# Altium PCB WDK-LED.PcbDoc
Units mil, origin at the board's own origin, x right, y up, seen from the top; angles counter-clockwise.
Board outline 1260 x 1260 mil, 2 copper layers (Top Layer, Bottom Layer); 26 components, 16 nets, 111 pads, 25 vias.
Unrouted connection lines stored in the file: 19.
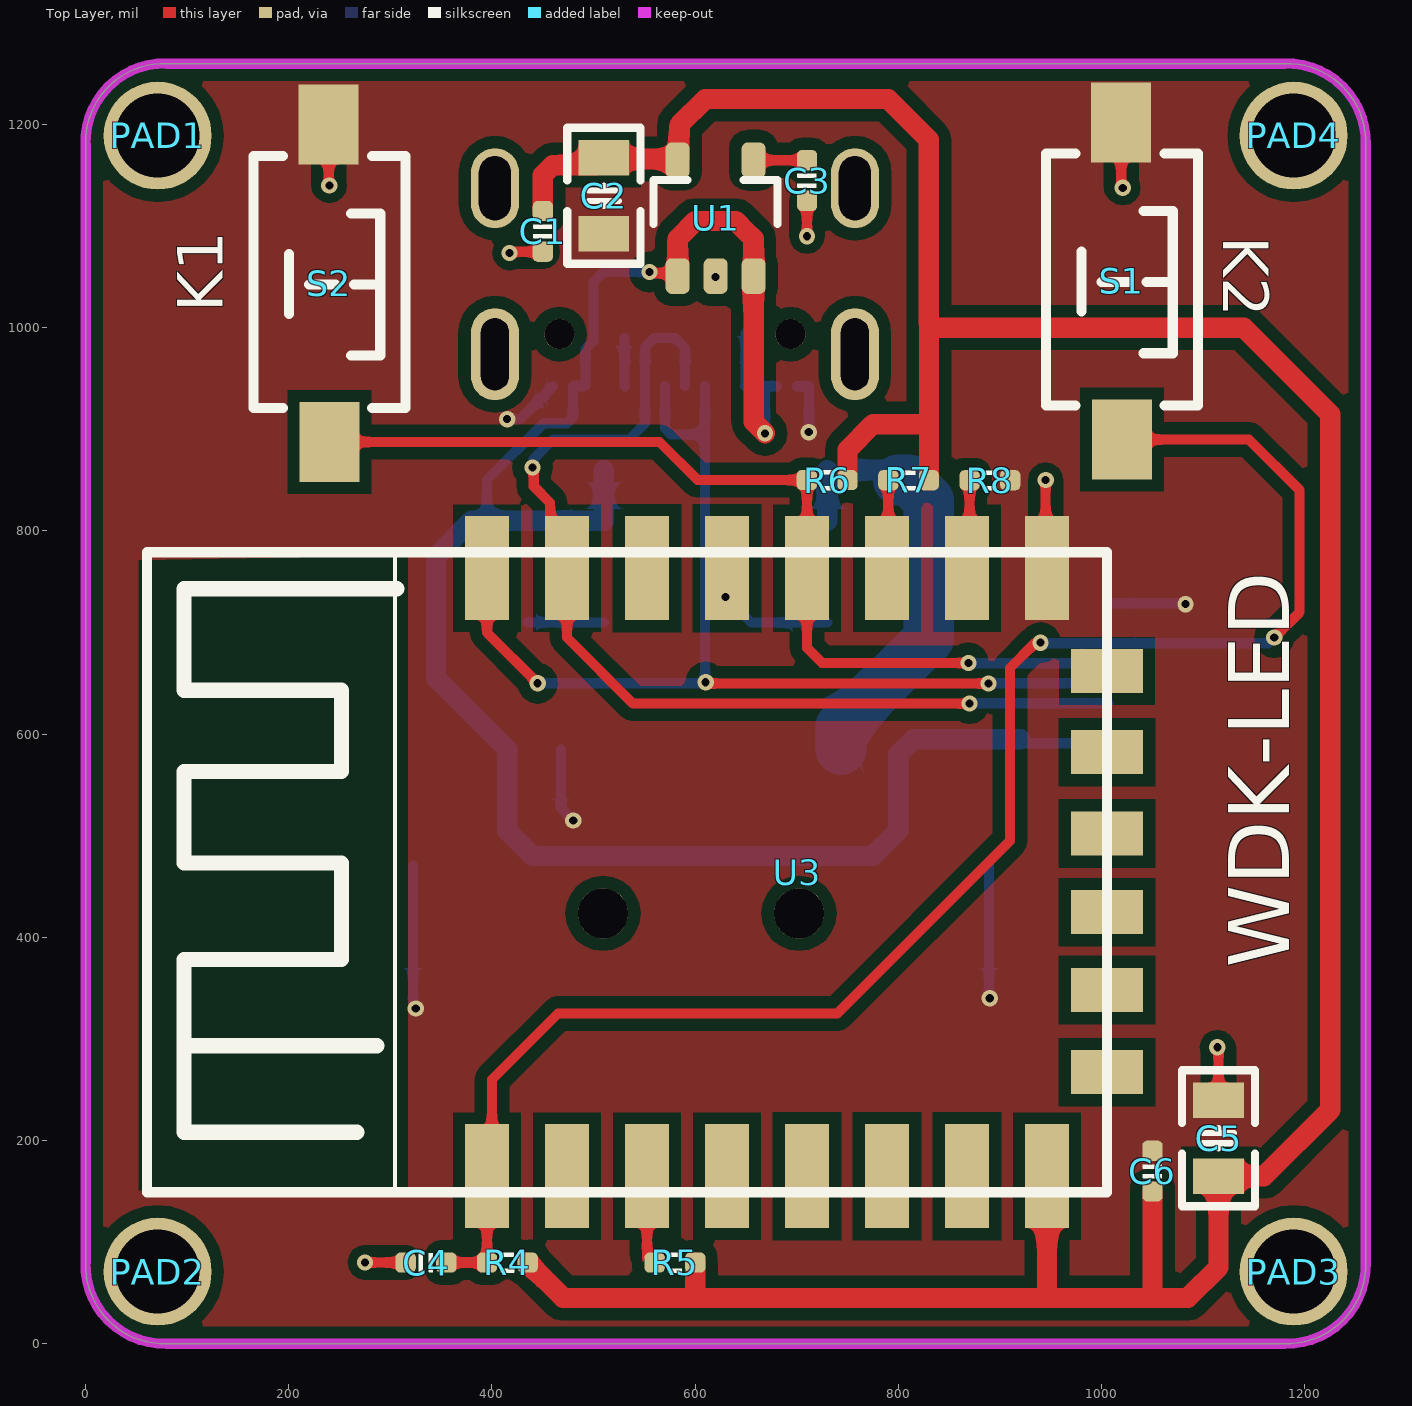
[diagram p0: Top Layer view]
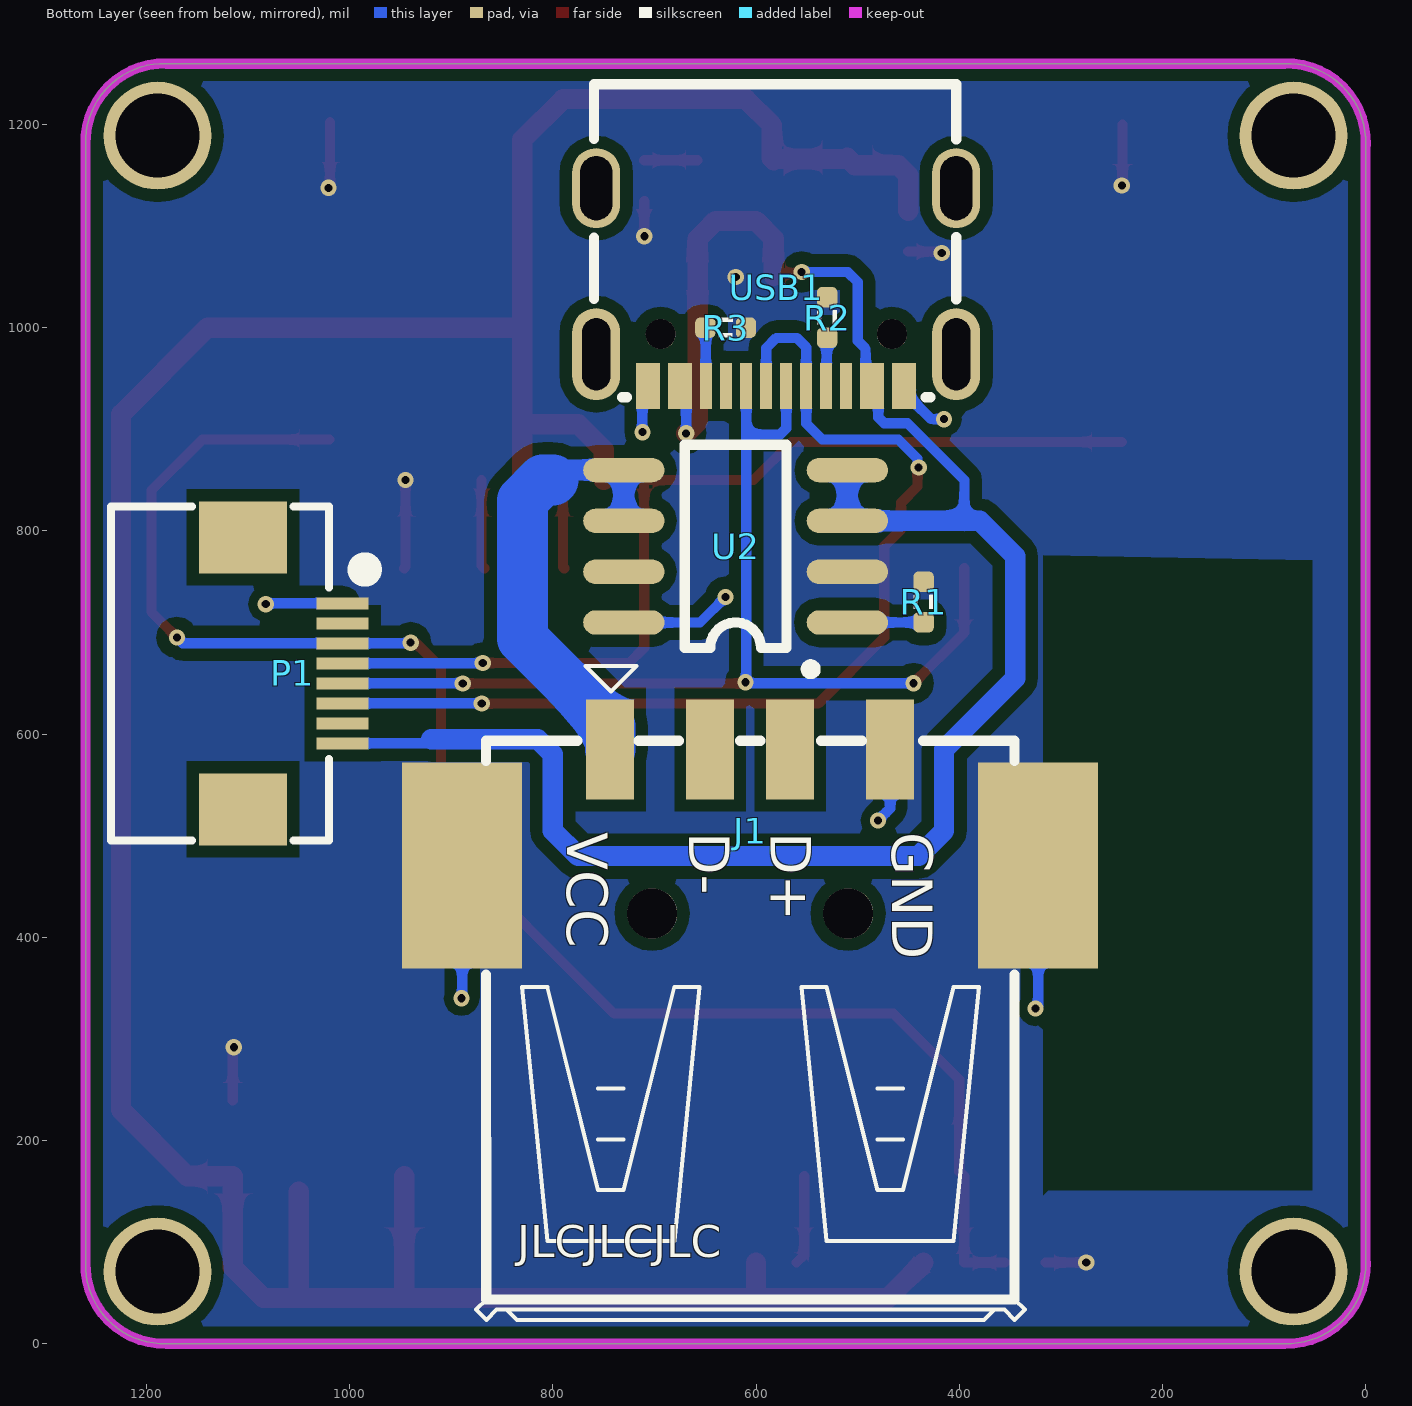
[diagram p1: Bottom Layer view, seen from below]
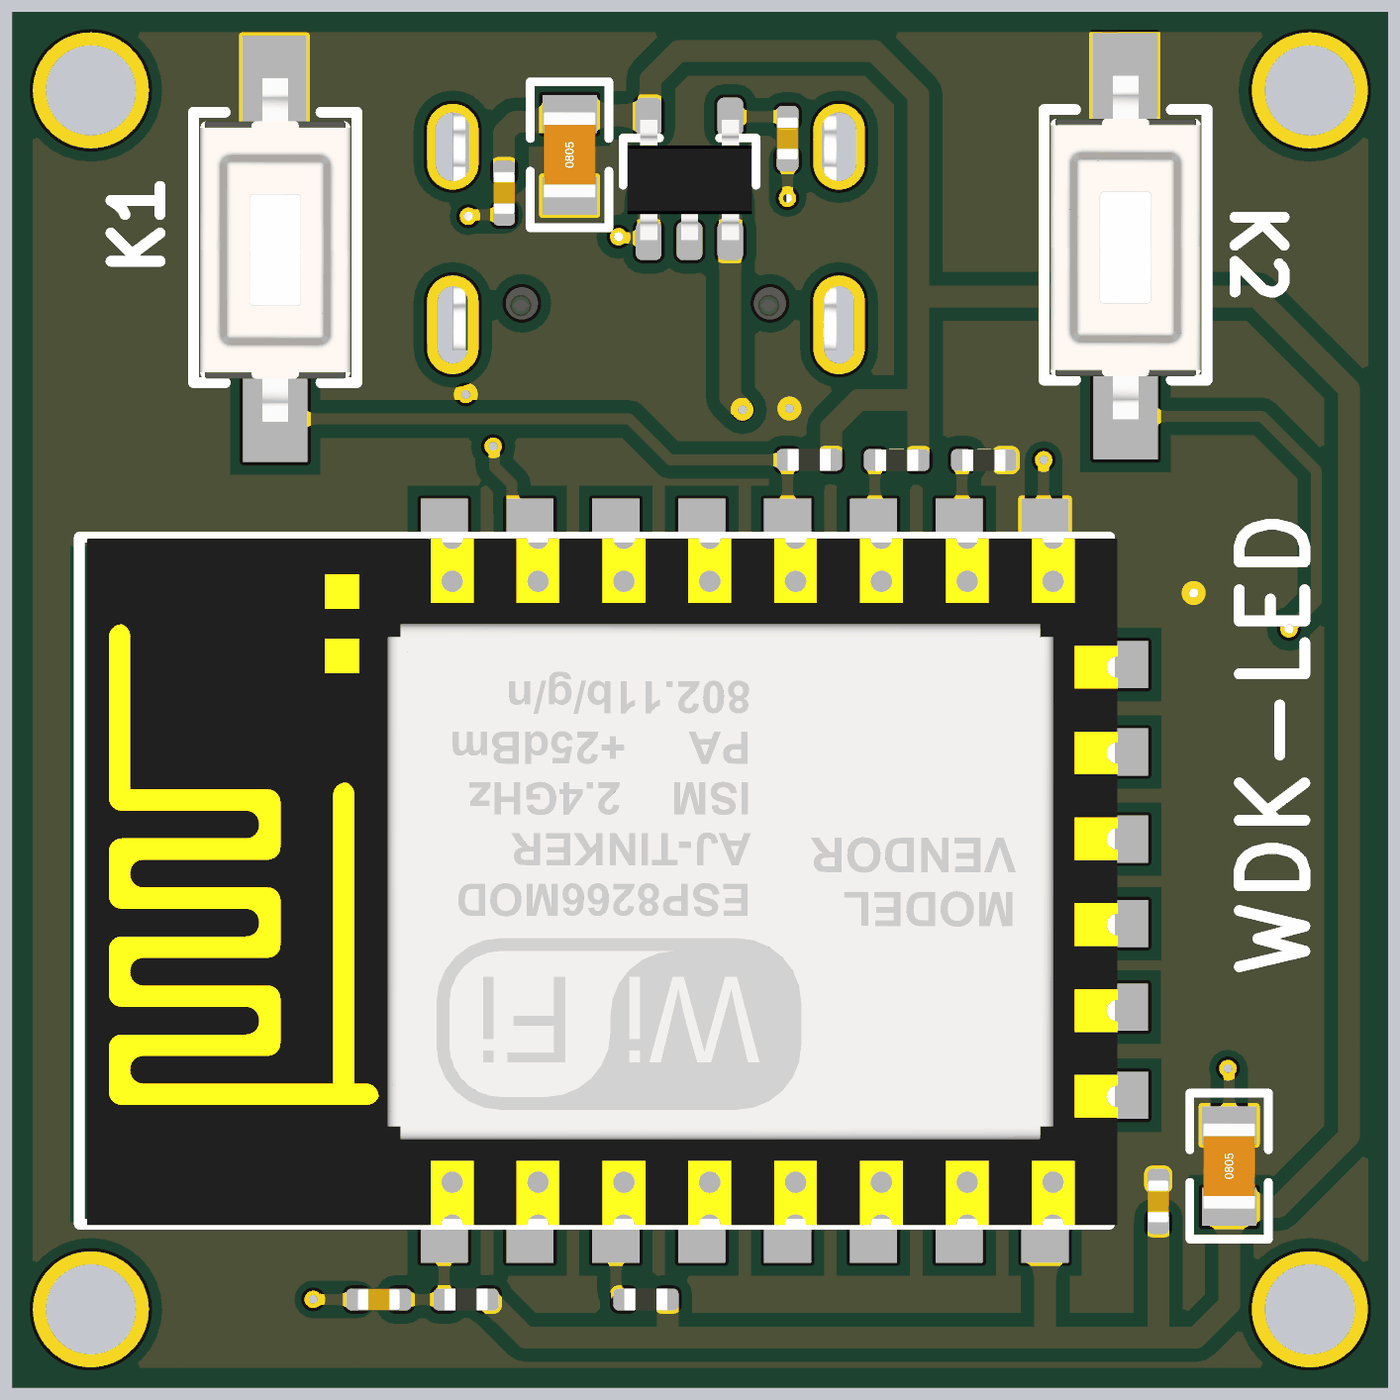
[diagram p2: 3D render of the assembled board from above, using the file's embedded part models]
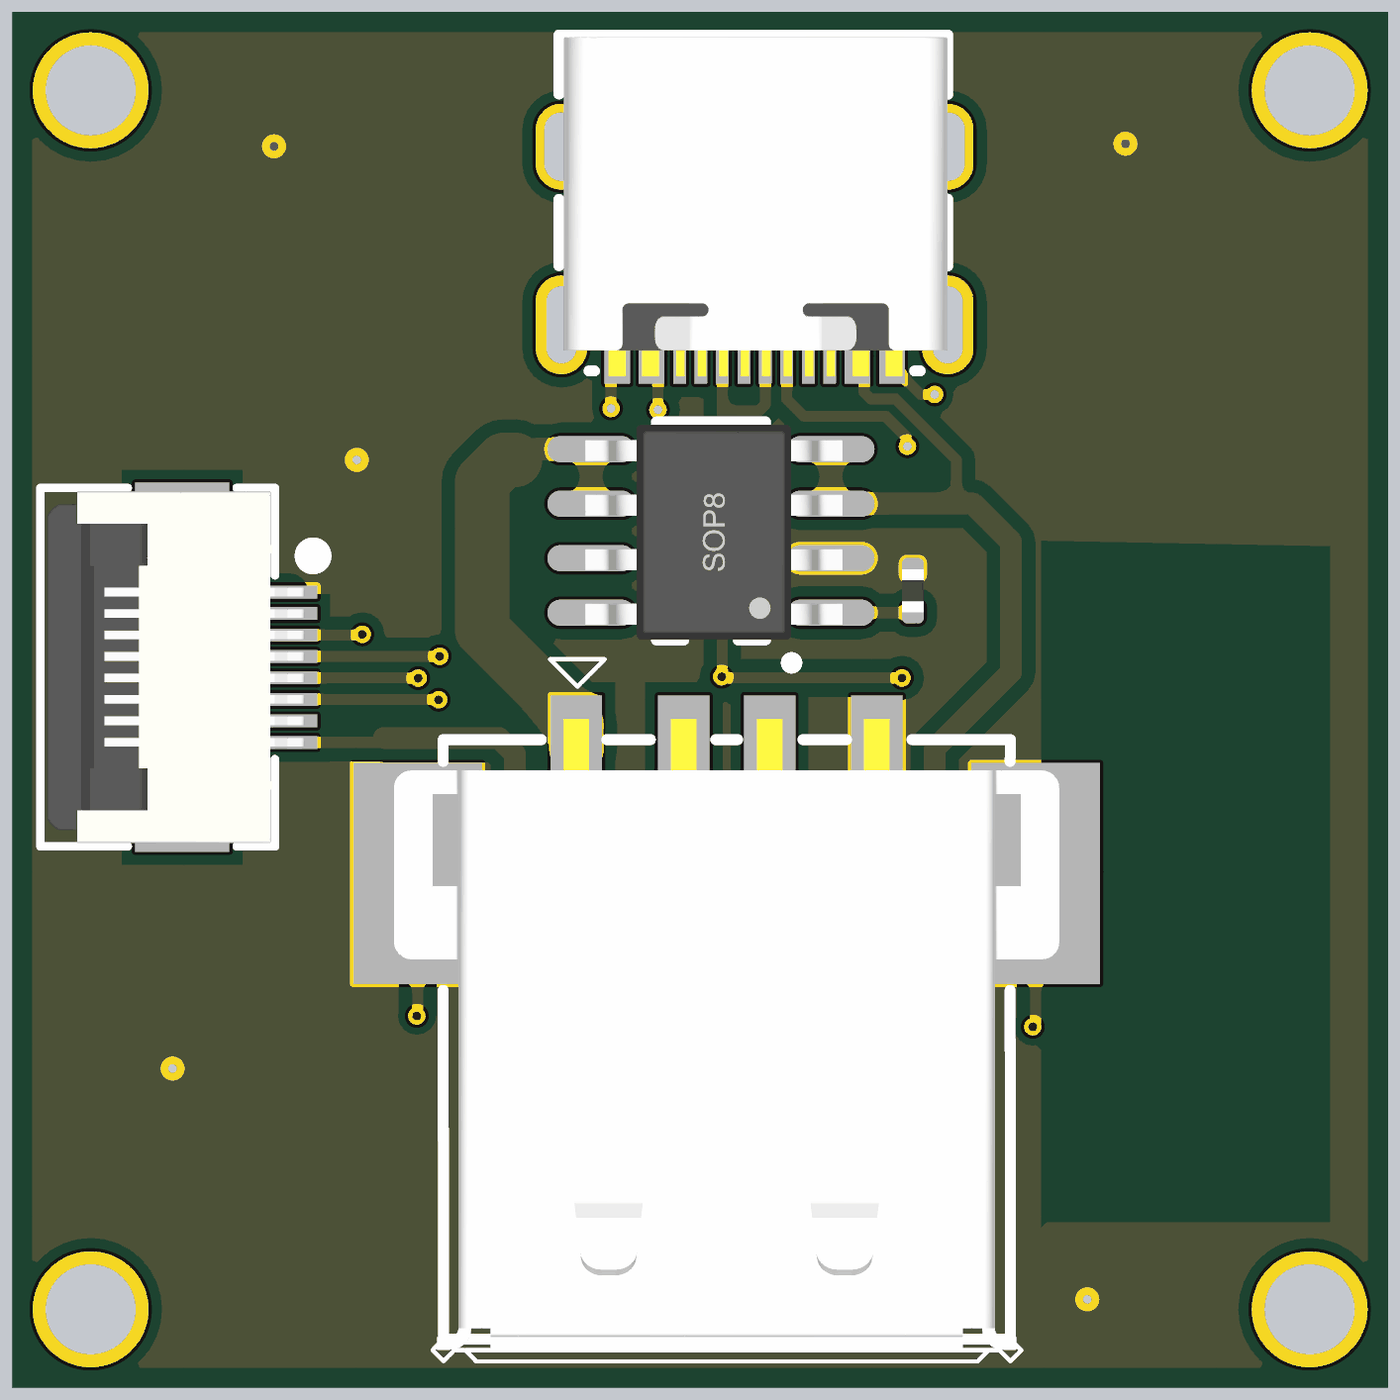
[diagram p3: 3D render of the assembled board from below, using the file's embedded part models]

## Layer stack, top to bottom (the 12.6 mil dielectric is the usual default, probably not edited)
Top Solder: solder mask 0.4, Solder Resist, Dk 3.5
Top Layer: signal copper 1.4
Dielectric 1: dielectric 12.6, FR-4, Dk 4.8
Bottom Layer: signal copper 1.4
Bottom Solder: solder mask 0.4, Solder Resist, Dk 3.5

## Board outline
0,80 ccw(c77.5,77.5) 80,0 1180,0 ccw(c1182.5,77.5) 1260,80 1260,1180 ccw(c1182.5,1182.5) 1180,1260 1180,1259.84 80,1259.84 80,1260 ccw(c77.5,1182.5) 0,1180 0.16,1180

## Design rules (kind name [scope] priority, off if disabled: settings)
Clearance [All] p1: gap=6 ignorepadtopadclearanceinfootprint=FALSE
ComponentClearance [All] p1: gap=0 collisioncheckmode=3 verticalgap=0 showdistances=FALSE
DiffPairsRouting [All] p1: maxlimit=9 minlimit=9 mostfreqgap=9 toplayer_minwidth=4 toplayer_maxwidth=4 toplayer_prefwidth=4 bottomlayer_minwidth=4 bottomlayer_maxwidth=4 bottomlayer_prefwidth=4 maxuncoupledlength=500
FanoutControl Fanout_BGA [All] p1: bgadir=Out bgaviamode=Centered fanoutstyle=Auto fanoutdirection=Alternating viagrid=1 // Fanout_BGA (Default Rule)
HoleSize [All] p1: absolutevalues=TRUE maxlimit=10000 minlimit=8 maxpercent=80.000 minpercent=20.000
MinimumSolderMaskSliver [All] p1 off: minsoldermaskwidth=2
PlaneClearance [All] p1: clearance=8
PlaneConnect [All] p1: planeconnectstyle=Direct reliefexpansion=20 reliefentries=4 reliefconductorwidth=10 reliefairgap=10
PolygonConnect [All] p1: connectstyle=Direct reliefconductorwidth=10 reliefentries=4 polygonreliefangle="90 Angle" airgapwidth=10
RoutingVias [All] p1: holewidth=8 width=16 viastyle="Through Hole" minholewidth=6 minwidth=12 maxholewidth=28 maxwidth=50
SilkToSilkClearance [All] p1: silktosilkclearance=0
SilkToSolderMaskClearance [IsPad] p1: minsilkscreentomaskgap=0 clearancetoexposedcopper=TRUE
SolderMaskExpansion [All] p1: expansion=3 istentingtop=FALSE
Width [All] p1: maxlimit=10000 minlimit=4 preferedwidth=10
21 further rules are at their usual default settings.

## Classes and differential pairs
net class GND: GND
net class POWER: 3V3 5V

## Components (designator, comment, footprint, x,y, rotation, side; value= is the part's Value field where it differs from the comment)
C1 "0.1uF" CAP_0402 450.16,1094.84 r90 top value=0.1u
C2 "10uF" C0805_L 510.16,1129.84 r90 top value=0.1u
C3 "10nF" CAP_0402 710.16,1144.84 r90 top value=0.1u
C4 "104" CAP_0402 335.16,79.84 r0 top
C5 "10uF" C0805_L 1115.15,202.25 r90 top
C6 "100nF" CAP_0402 1050.16,169.84 r90 top
J1 "USB-A" USB-A/S_C 605.79,423.43 r180 bottom locked
P1 "DowmLoad" "FPC0.5 2H-WS-8P" 1105.16,659.84 r270 bottom
PAD1 "PAD" M2#1 70.16,1184.84 r90 top
PAD2 "PAD" M2#2 70.16,69.84 r90 top
PAD3 "PAD" M2#3 1190.16,79.84 r90 top
PAD4 "PAD" M2#4 1185.16,1189.84 r90 top
R1 "2K" RES_0402 435,730 r270 bottom
R2 "5.1K" RES_0402 530,1010 r270 bottom value=22R
R3 "5.1K" RES_0402 630,1000 r0 bottom value=22R
R4 "10K" RES_0402 415.16,79.84 r0 top
R5 "10K" RES_0402 580.16,79.84 r180 top
R6 "10K" RES_0402 730,850 r0 top
R7 "10K" RES_0402 810.16,849.84 r0 top
R8 "10K" RES_0402 890.16,849.84 r180 top
S1 "SW-PB" "SW SMD-3*6*2.5" 1020.16,1044.84 r270 top
S2 "SW-PB" "SW SMD-3*6*2.5" 240.16,1042.53 r270 top
U1 "LP2992 3V3" SOT23-5 620.16,1109.84 r90 top
U2 "cn5711" SOP8 511.16,708.84 r0 bottom locked
U3 "ESP-12F" ESP-12F 655.16,299.84 r90 top locked
USB1 "Type-C" USB-C-SMD_16P 580.16,1039.84 r180 bottom locked

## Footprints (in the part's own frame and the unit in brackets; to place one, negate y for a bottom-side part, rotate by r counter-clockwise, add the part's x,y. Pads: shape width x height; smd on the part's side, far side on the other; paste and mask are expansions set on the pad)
C0805_L [mil] "无极性贴片电容"
  rect 35x50 smd: 1(-37.4,0) 2(37.4,0)
  silkscreen extent -67,-36 67,36, body extent -39,-24 39,24, height 22
CAP_0402 [mil]
  rrect50% 20x20 smd: 1(-20,0) 2(20,0)
  silkscreen extent -7,-9 7,9, body extent -20,-10 20,10, height 20
ESP-12F [mm]
  rect 2.6x1.1 smd: 1(-3.429,6.604) 2(-3.429,4.604) 3(-3.429,2.604) 4(-3.429,0.604) 5(-3.429,-1.396) 6(-3.429,-3.396) 7(-3.429,-5.396) 8(-3.429,-7.396) 15(11.771,-7.396) 16(11.771,-5.396) 17(11.771,-3.396) 18(11.771,-1.396) 19(11.771,0.604) 20(11.771,2.604) 21(11.771,4.604) 22(11.771,6.604)
  rect 1.1x1.8 smd: 9(-0.829,-8.896) 10(1.225,-8.893) 11(3.171,-8.896) 12(5.14,-8.896) 13(7.171,-8.896) 14(9.204,-8.896)
  silkscreen extent -3.83,-8.9 12.17,15.1, body extent -3.86,-9.09 12.15,14.92, height 2.65
"FPC0.5 2H-WS-8P" [mm] "长：8.2mm，宽：5.2mm，高：2mm 淘宝ID:黄晶宝石   店铺网址:https://shop463601444.taobao.com"
  rect 1.8x2.2 smd: 0(-3.4,0) 0(3.4,0)
  rect 0.3x1.3 smd: 1(-1.75,2.497) 2(-1.25,2.497) 3(-0.75,2.497) 4(-0.25,2.497) 5(0.25,2.497) 6(0.75,2.497) 7(1.25,2.497) 8(1.75,2.497)
  silkscreen extent -4.17,-3.3 4.17,3.23, body extent -4.1,-3.15 4.1,2.85, height 2
M2#1 [mm]
  round 2.7 hole 2.1: 1(0.105,-0.022)
M2#2 [mm]
  round 2.7 hole 2.1: 1(0.026,-0.022)
M2#3 [mm]
  round 2.7 hole 2.1: 1(-0.228,0.026)
M2#4 [mm]
  round 2.7 hole 2.1: 1(-0.022,-0.101)
RES_0402 [mil]
  rrect50% 20x20 smd: 1(-20,0) 2(20,0)
  silkscreen extent -7,-10 7,10, body extent -20,-10 20,10, height 14
SOP8 [mil]
  oval 80x24 smd: 1(-1,-1) 2(-1,-51) 3(-1,-101) 4(-1,-151) 5(219,-151) 6(219,-101) 7(219,-51) 8(219,-1)
  silkscreen extent 30,-176 159,50, body extent -12,-173 225,24, height 75
SOT23-5 [mm]
  rrect50% 0.889x0.6 smd: 1(-1.5,0.95) 2(-1.5,0) 3(-1.5,-0.95) 4(1.396,-0.95) 5(1.396,0.95)
  silkscreen extent -0.2,-1.55 0.9,1.55, body extent -1.48,-1.45 1.32,1.45, height 1.2
"SW SMD-3*6*2.5" [mm] "3*6*2.5mm"
  rect 2x1.5 smd: 1(-3.996,-0.02) 2(3.937,0)
  silkscreen extent -3.21,-1.9 3.09,1.9, body extent -4,-1.75 4,1.75, height 2.59
USB-A/S_C [mm] "A型贴片母头， 淘宝ID:黄晶宝石"
  rect 1.2x2.5 smd: 1(-3.5,4.1) 2(-1,4.1) 3(1,4.1) 4(3.5,4.1)
  rect 3x5.15 smd: 4(-7.2,1.2) 4(7.2,1.2)
  round 1.25 hole 1.25 unplated: 7(-2.45,0) 8(2.45,0)
  silkscreen extent -6.85,-10.17 6.86,6.19, body extent -7.75,-9.9 7.75,4.8, height 7.4
USB-C-SMD_16P [mm] "封装库来自淘宝ID:黄晶宝石"
  oval 1.2x2.3 hole 0.7 slot 1.8 at 90 deg: 0(-4.5,-1.675) 0(4.5,-1.675)
  oval 1.2x2 hole 0.8 slot 1.6 at 90 deg: 0(-4.5,2.475) 0(4.5,2.475)
  rect 0.3x1.15 smd: A1(3.35,-2.473) A4(2.55,-2.471) A5(1.25,-2.475) A6(0.25,-2.475) A7(-0.25,-2.473) A9(-2.55,-2.475) A12(-3.35,-2.475) B1(-3.05,-2.475) B4(-2.25,-2.475) B5(-1.75,-2.475) B6(-0.75,-2.475) B7(0.75,-2.473) B9(2.25,-2.471) B12(3.05,-2.473)
  rect 0.3x1.148 smd: A8(1.75,-2.475) B8(-1.25,-2.475)
  round 0.75 hole 0.75 unplated: ""(-2.89,-1.175) ""(2.89,-1.175)
  silkscreen extent -4.56,-2.75 4.5,5.08, body extent -4.44,-2.87 4.5,5.03, height 3.25

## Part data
C1 C2 C3: library part 电容-0402, "Capacitor"
C4 C5 C6: library part C, "无极性贴片电容"
J1: library part USB, "USB接口"
P1: library part "Header 8", "Header, 8-Pin"
PAD1 PAD2 PAD3 PAD4: "M2通孔"
R1 R4 R5 R6 R7 R8: library part R, "贴片电阻"
R2 R3: library part 电阻-0402, "Resistor"
S1 S2: "微动开关"
U1: library part LP2992, "LDO"
U3: Manufacturer=安信可
USB1: library part USB-Type-C-TOP

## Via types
v1: diameter 16, hole 8, Top Layer to Bottom Layer, 25 vias

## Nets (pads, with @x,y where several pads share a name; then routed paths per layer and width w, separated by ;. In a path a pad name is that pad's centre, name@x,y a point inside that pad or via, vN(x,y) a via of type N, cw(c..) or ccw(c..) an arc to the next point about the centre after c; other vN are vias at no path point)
3V3: C1.2 C2.2 C5.1 C6.1 R4.2 R5.1 R6.2 R7.2 U1.5 U3.8 | length 3248.4
  Top Layer w20: R4.2 470,45 605,45 ; C1.2 450.16,1149.84 450,1150 460,1160 502.92,1160 C2.2 511.39,1166.01 581.53,1166.01 U1.5 584.57,1166.6 584.57,1199.57 610,1225 790,1225 830,1185 830,1005 830.16,1004.84 ; R5.1 600.16,49.84 605,45 ; R6.2 750,880 775,905 825,905 ; R7.2 830.16,1004.84 ; U3.8 946.34,48.66 950,45 ; C6.1 1050.16,45.16 1050,45 ; 605,45 950,45 ; 830.16,1004.84 835,1000 1140,1000 1225,915 1225,230 1159.84,164.84 C5.1 1115.16,75.16 1085,45 1050,45 ; 950,45 1050,45
5V: P1.8 U1.1 U1.3 U2.3 U2.4 USB1.A4 USB1.A9 USB1.B4 USB1.B9 | length 1992
  Top Layer w10: v1(555.13,1054.71) 556.28,1053.56 579.98,1053.56 U1.1
  Top Layer w20: U1.1 582.76,1087.76 600,1105 640,1105 649.97,1095.03 657.56,1087.44 U1.3 657.56,907.22 v1(668.8,895.98)
  Bottom Layer w10: 395,809.84 395,850 451,906 473.91,906 479.76,911.86 USB1.A4 USB1.B9 492.15,943.14 492.15,979.14 500,987 500,1045 509.71,1054.71 v1(555.13,1054.71) ; v1(668.8,895.98) 668.8,942.35 USB1.B4 USB1.A9 ; 920,595 924.06,590.94 P1.8
  Bottom Layer w20: U2.4 U2.3 395,809.84 379.84,809.84 345,775 345,655 415,585 415,505 440,480 775,480 800,505 800,580 815,595 920,595
EN: C4.2 P1.3 R4.1 S1.2 U3.1 | length 1623.3
  Top Layer w10: C4.2 R4.1 U3.1 400,169.69 400,260 465,325 740,325 910,495 910,665 933.85,688.85 938.85,688.85 v1(940,690) ; S1.2 1145.16,889.84 1195,840 1195,720 v1(1170,695)
  Bottom Layer w10: v1(940,690) 940.63,689.37 P1.3 1164.37,689.37 v1(1170,695)
GND: C1.1 C2.1 C3.1 C4.1 C5.2 C6.2 J1.4 P1.1 R1.1 R2.1 R3.1 R8.1 S1.1 S2.1 U1.2 U2.2 U3.15 USB1.A1 USB1.A12 USB1.B1 USB1.B12 | length 913.9
  Top Layer w10: S2.1 239.37,1140.63 v1(240,1140) ; v1(275,80) 275.16,79.84 C4.1 ; v1(417.29,1073.47) 418.66,1074.84 C1.1 ; v1(620,1050) 620.16,1050.16 U1.2 ; v1(710,1090) 710.08,1090.08 710.08,1124.76 C3.1 ; v1(945,850) 945,764.61 U3.15 ; S1.1 1019.37,1139.16 v1(1020.92,1137.61) ; v1(1114.01,291.72) 1115.16,290.56 C5.2
  Bottom Layer w10: J1.4@322.32,470.67 322.32,332.68 v1(325,330) ; v1(415,910) 427.61,910 USB1.B12 ; J1.4@467.99,584.84 467.99,527.01 v1(480,515) ; USB1.B1 USB1.A12 712.05,897.39 v1(711.82,897.16) ; J1.4@889.25,470.67 889.25,340.75 v1(890,340) ; P1.1 1081.75,728.74 v1(1082.57,727.91)
GPIO0: P1.4 R6.1 S2.2 U3.18 | length 953.6
  Top Layer w10: S2.2 565,887.53 602.53,850 R6.1 710.16,849.84 710.16,763.31 U3.18 710.12,684.88 725,670 865,670 865.14,669.86 v1(868.97,669.86)
  Bottom Layer w10: v1(868.97,669.86) 869.06,669.77 1006.76,669.77 P1.4
GPIO4: U2.8 U3.19 | length 110.6
  Bottom Layer w10: v1(630,735) 655.16,709.84 U2.8
LED+: J1.1 U2.5 U2.6 | length 419.2
  Bottom Layer w20: U2.6 U2.5 ; U2.5@755.16,860.16 805.16,860.16
  Bottom Layer w50: J1.1 743.58,607.68 830,694.09 830,830 810,850 800,850
NetC3_2: C3.2 U1.4 | length 52.6
  Top Layer w10: U1.4@657.59,1164.81 C3.2
NetR1_2: R1.2 U2.1 | length 75.2
  Bottom Layer w10: R1.2 435.08,709.92 510.08,709.92 U2.1
NetR2_2: R2.2 USB1.A5 | length 48
  Bottom Layer w10: R2.2 530.47,989.53 530.47,942.87 USB1.A5
NetR3_2: R3.2 USB1.B5 | length 53
  Bottom Layer w10: USB1.B5 649.53,942.88 649.53,994.53 R3.2@650,995
NetR5_2: R5.2 U3.3 | length 88.1
  Top Layer w10: U3.3 552.64,87.36 R5.2
NetR7_1: R7.1 U3.17 | length 87.1
  Top Layer w10: U3.17 790.16,764.57 R7.1
NetR8_2: R8.2 U3.16 | length 87.6
  Top Layer w10: U3.16 870.16,765.83 R8.2
RXD: P1.6 U3.21 USB1.A7 USB1.B7 | length 1034.4
  Top Layer w10: v1(440,862.5) 441.15,861.35 441.15,843.85 457.24,827.76 457.24,801.65 473.9,785 U3.21 473.9,695 538.9,630 v1(870,630)
  Bottom Layer w10: v1(440,862.5) 441.15,863.65 441.15,871.15 460,890 535,890 550.63,905.63 USB1.B7 550.63,980.63 560,990 580,990 590,980 USB1.A7 ; v1(870,630) 870.31,630.31 P1.6
TXD: P1.5 U3.22 USB1.A6 USB1.B6 | length 1070.7
  Top Layer w10: U3.22 395.16,699.84 v1(445,650) ; v1(610.35,651.06) 611.57,649.84 v1(888.73,649.84)
  Bottom Layer w10: v1(445,650) v1@610,650 ; USB1.A6 570.31,900.86 576.17,895 609.69,895 ; v1@609.69,651.06 609.69,895 ; USB1.B6 609.69,895 ; v1(888.73,649.84) 888.89,650 P1.5
pads on no net: J1.2 J1.3 J1.7 J1.8 P1.0 P1.2 P1.7 PAD1.1 PAD2.1 PAD3.1 PAD4.1 U2.7 U3.2 U3.4 U3.5 U3.6 U3.7 U3.9 U3.10 U3.11 U3.12 U3.13 U3.14 U3.20 USB1. USB1.0 USB1.A8 USB1.B8

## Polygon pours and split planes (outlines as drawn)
GND on Bottom Layer "GND_L02_P000" (solid, pour order 0): 0,1260 1260,1260 1260,0 0,0
GND on Top Layer "GND_L01_P001" (solid, pour order 1): 0,1260 1260,1260 1260,0 0,0

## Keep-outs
Keep-Out Layer:
  lines w10: 0,80 ccw(c77.5,77.5) 80,0 1180,0 ccw(c1182.5,77.5) 1260,80 1260,1180 ccw(c1182.5,1182.5) 1180,1260 ; 0,1180 cw(c77.5,1182.5) 80,1260 ; 0.16,80 0.16,1180 ; 80,1259.84 1180,1259.84

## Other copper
Multi-Layer:
  pour cut-out: 52.34,770.88 52.34,150.88 312.34,150.88 317.34,145.88 317.34,775.88

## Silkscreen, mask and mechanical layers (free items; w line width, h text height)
Top Overlay:
  text "K2" at 1120,1089.98 h45 r270
  text "K1" at 135,1015 h45 r90
  text "WDK-LED" at 1185,370 h60 r90
Bottom Overlay:
  text "JLCJLCJLC" at 835,85 h31.5
Mechanical 1:
  lines w10: 80,0 cw(c77.5,77.5) 0,80 0.16,1180 0,1180 cw(c77.5,1182.5) 80,1260 80,1259.84 1180,1259.84 1180,1260 cw(c1182.5,1182.5) 1260,1180 ; 80,0 1180,0 ; 80,0 80,0 ; 1180,0 ccw(c1182.5,77.5) 1260,80 ; 1180,0 1180,0 ; 1260,80 1260,1180 ; 1260,80 1260,80 ; 1260,1180 1260,1180
Drill Drawing:
  circle w10: c85.62,2412.28 r33.33
  lines w10: 52.29,1795.61 68.96,1795.61 68.96,1778.94 102.29,1778.94 102.29,1795.61 118.96,1795.61 118.96,1828.94 102.29,1828.94 102.29,1845.61 68.96,1845.61 68.96,1828.94 52.29,1828.94 52.29,1795.61 ; 52.29,1928.94 85.62,1945.61 118.96,1928.94 102.29,1962.28 118.96,1995.61 85.62,1978.94 52.29,1995.61 68.96,1962.28 52.29,1928.94 ; 52.29,2078.94 118.96,2078.94 118.96,2145.61 52.29,2145.61 52.29,2078.94 ; 52.29,2295.61 118.96,2295.61 85.62,2228.94 52.29,2295.61 ; 52.29,2545.61 68.96,2545.61 85.62,2528.94 102.29,2545.61 118.96,2545.61 102.29,2562.28 118.96,2578.94 102.29,2578.94 85.62,2595.61 68.96,2578.94 52.29,2578.94 68.96,2562.28 52.29,2545.61
  lines w15: -7.5,1733.94 12920.88,1733.94 ; -7.5,2633.94 12920.88,2633.94 ; 543.38,1583.94 543.38,2783.94 ; 1083.24,1583.94 1083.24,2783.94 ; 2182.92,1583.94 2182.92,2783.94 ; 2688.79,1583.94 2688.79,2783.94 ; 3422.59,1583.94 3422.59,2783.94 ; 4922.14,1583.94 4922.14,2783.94 ; 5511.99,1583.94 5511.99,2783.94 ; 6257.79,1583.94 6257.79,2783.94 ; 6907.62,1583.94 6907.62,2783.94 ; 7761.38,1583.94 7761.38,2783.94 ; 9094.99,1583.94 9094.99,2783.94 ; 10428.6,1583.94 10428.6,2783.94 ; 11518.28,1583.94 11518.28,2783.94 ; -7.5,1583.94 12920.88,1583.94 12920.88,2783.94 -7.5,2783.94 -7.5,1583.94
  text "Symbol" at 82.5,2678.94 h72
  text "Count" at 588.38,2678.94 h72
  text "Hole Size" at 1128.24,2678.94 h72
  text "Plated" at 2227.92,2678.94 h72
  text "Hole Type" at 2733.79,2678.94 h72
  text "Drill Layer Pair" at 3467.59,2678.94 h72
  text "Via/Pad" at 4967.14,2678.94 h72
  text "Pad Shape" at 5556.99,2678.94 h72
  text "Template" at 6302.79,2678.94 h72
  text "Description" at 6952.62,2678.94 h72
  text "Hole Tolerance (+)" at 7806.38,2678.94 h72
  text "Hole Tolerance (-)" at 9139.99,2678.94 h72
  text "Hole Length" at 10473.6,2678.94 h72
  text "Routed Path Length" at 11563.28,2678.94 h72
  text "2" at 588.38,2528.94 h60
  text "27.56mil (0.700mm)" at 1128.24,2528.94 h60
  text "PTH" at 2227.92,2528.94 h60
  text "Slot" at 2733.79,2528.94 h60
  text "Top Layer - Bottom Layer" at 3467.59,2528.94 h60
  text "Pad" at 4967.14,2528.94 h60
  text "Rounded" at 5556.99,2528.94 h60
  text "(Mixed)" at 6302.79,2528.94 h60
  text "70.87mil (1.800mm)" at 10473.6,2528.94 h60
  text "43.31mil (1.100mm)" at 11563.28,2528.94 h60
  text "2" at 588.38,2378.94 h60
  text "29.53mil (0.750mm)" at 1128.24,2378.94 h60
  text "NPTH" at 2227.92,2378.94 h60
  text "Round" at 2733.79,2378.94 h60
  text "Top Layer - Bottom Layer" at 3467.59,2378.94 h60
  text "Pad" at 4967.14,2378.94 h60
  text "Rounded" at 5556.99,2378.94 h60
  text "c75hn75" at 6302.79,2378.94 h60
  text "-" at 10473.6,2378.94 h60
  text "-" at 11563.28,2378.94 h60
  text "2" at 588.38,2228.94 h60
  text "31.50mil (0.800mm)" at 1128.24,2228.94 h60
  text "PTH" at 2227.92,2228.94 h60
  text "Slot" at 2733.79,2228.94 h60
  text "Top Layer - Bottom Layer" at 3467.59,2228.94 h60
  text "Pad" at 4967.14,2228.94 h60
  text "Rounded" at 5556.99,2228.94 h60
  text "(Mixed)" at 6302.79,2228.94 h60
  text "62.99mil (1.600mm)" at 10473.6,2228.94 h60
  text "31.50mil (0.800mm)" at 11563.28,2228.94 h60
  text "2" at 588.38,2078.94 h60
  text "49.21mil (1.250mm)" at 1128.24,2078.94 h60
  text "NPTH" at 2227.92,2078.94 h60
  text "Round" at 2733.79,2078.94 h60
  text "Top Layer - Bottom Layer" at 3467.59,2078.94 h60
  text "Pad" at 4967.14,2078.94 h60
  text "Rounded" at 5556.99,2078.94 h60
  text "c125hn125" at 6302.79,2078.94 h60
  text "-" at 10473.6,2078.94 h60
  text "-" at 11563.28,2078.94 h60
  text "4" at 588.38,1928.94 h60
  text "82.68mil (2.100mm)" at 1128.24,1928.94 h60
  text "PTH" at 2227.92,1928.94 h60
  text "Round" at 2733.79,1928.94 h60
  text "Top Layer - Bottom Layer" at 3467.59,1928.94 h60
  text "Pad" at 4967.14,1928.94 h60
  text "Rounded" at 5556.99,1928.94 h60
  text "c270h210" at 6302.79,1928.94 h60
  text "-" at 10473.6,1928.94 h60
  text "-" at 11563.28,1928.94 h60
  text "25" at 588.38,1778.94 h60
  text "8.00mil (0.203mm)" at 1128.24,1778.94 h60
  text "PTH" at 2227.92,1778.94 h60
  text "Round" at 2733.79,1778.94 h60
  text "Top Layer - Bottom Layer" at 3467.59,1778.94 h60
  text "Via" at 4967.14,1778.94 h60
  text "Rounded" at 5556.99,1778.94 h60
  text "v41h20" at 6302.79,1778.94 h60
  text "-" at 10473.6,1778.94 h60
  text "-" at 11563.28,1778.94 h60
  text "37 Total" at 588.38,1628.94 h60
  text "Slot definitions :" at 82.5,1483.97 h60
  text "Routed Path Length" at 1115.19,1483.97 h60
  text "= Calculated from tool start centre position to tool end centre position." at 2217.86,1483.97 h60
  text "Hole Length" at 1115.19,1383.99 h60
  text "= Routed Path Length + Tool Size = Slot length as defined in the PCB layout" at 1807.99,1383.99 h60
